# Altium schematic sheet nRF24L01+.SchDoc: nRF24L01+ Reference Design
size Letter
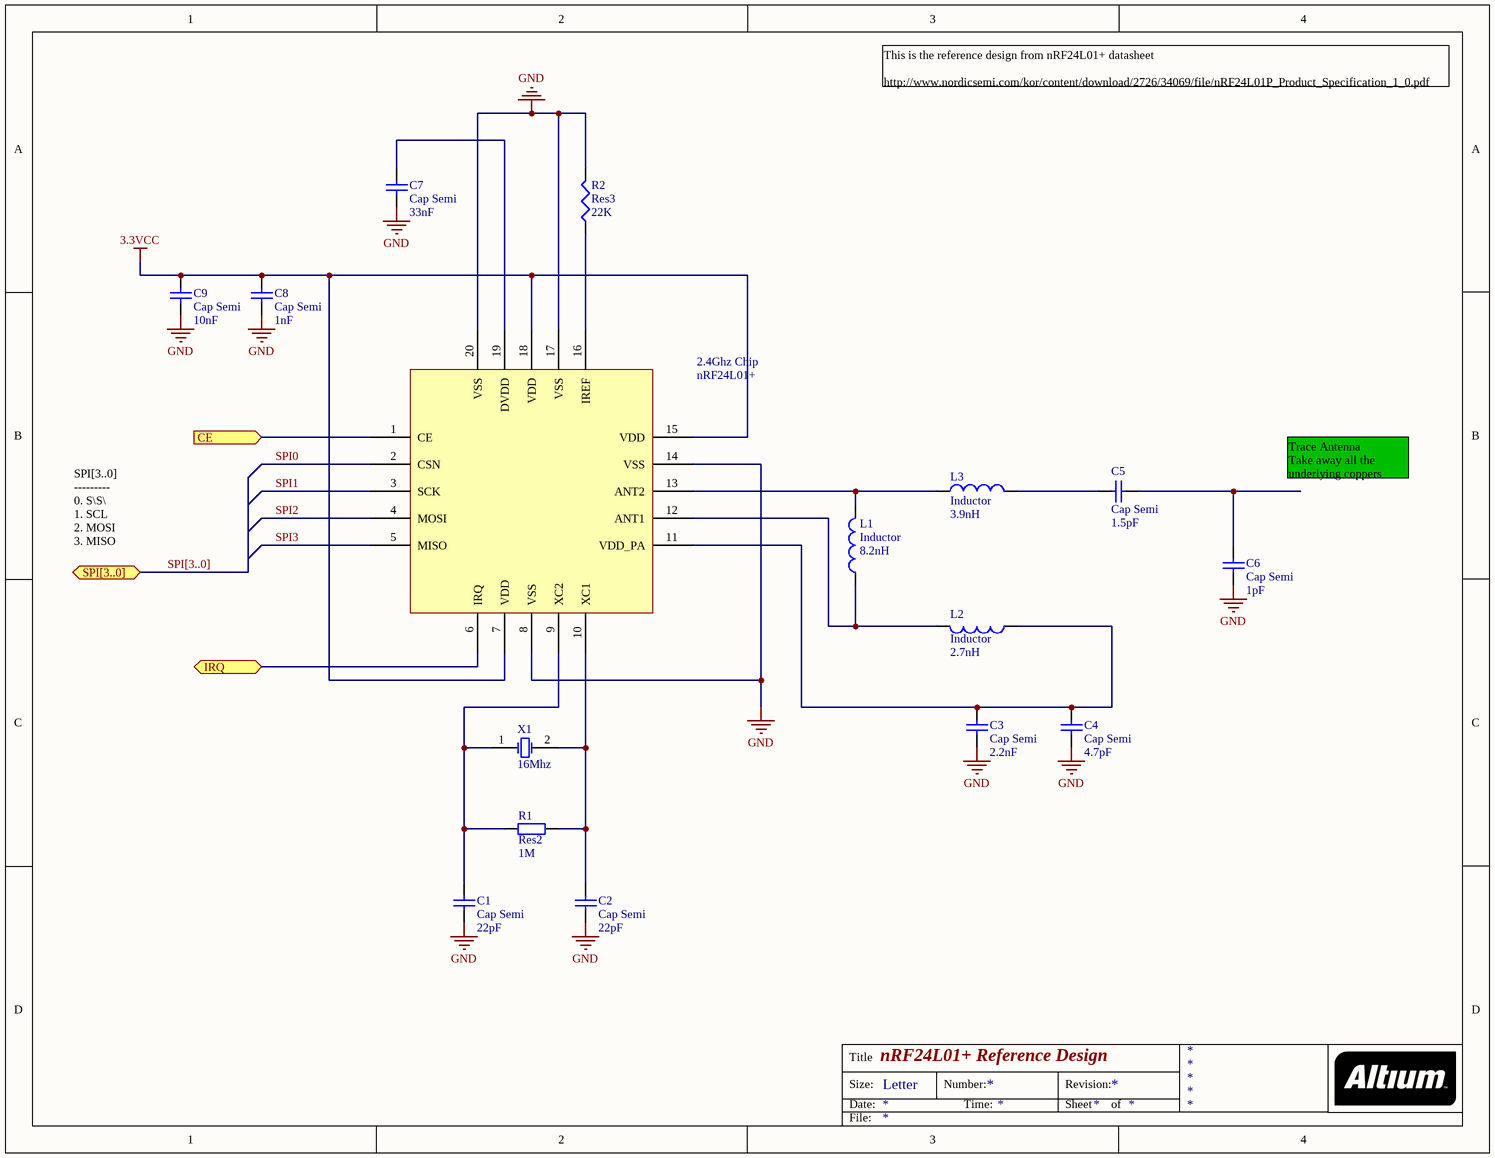
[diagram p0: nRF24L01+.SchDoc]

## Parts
2.4Ghz_Chip  nRF24L01+  [nRF24L01+]
C1  Cap Semi  value 22pF  [CAPC2012N]
C2  Cap Semi  value 22pF  [CAPC2012N]
C3  Cap Semi  value 2.2nF  [CAPC2012N]
C4  Cap Semi  value 4.7pF  [CAPC2012N]
C5  Cap Semi  value 1.5pF  [CAPC2012N]
C6  Cap Semi  value 1pF  [CAPC2012N]
C7  Cap Semi  value 33nF  [CAPC2012N]
C8  Cap Semi  value 1nF  [CAPC2012N]
C9  Cap Semi  value 10nF  [CAPC2012N]
L1  Inductor  value 8.2nH  [INDC1608N]
L2  Inductor  value 2.7nH  [INDC1608N]
L3  Inductor  value 3.9nH  [INDC1608N]
R1  Res2  value 1M  [RESC2012N]
R2  Res3  value 22K  [RESC2012N]
X1  16Mhz  [HC-49U - Through Hole]

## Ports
CE (in), IRQ, SPI[3..0] (bidir)

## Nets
3.3VCC: 2.4Ghz_Chip.7(VDD) 2.4Ghz_Chip.15(VDD) 2.4Ghz_Chip.18(VDD) C8.2 C9.2
GND: 2.4Ghz_Chip.8(VSS) 2.4Ghz_Chip.14(VSS) 2.4Ghz_Chip.17(VSS) 2.4Ghz_Chip.20(VSS) C1.1 C2.1 C3.1 C4.1 C6.1 C7.1 C8.1 C9.1 R2.2
CE: 2.4Ghz_Chip.1(CE) ; port CE
IRQ: 2.4Ghz_Chip.6(IRQ) ; port IRQ
SPI0: 2.4Ghz_Chip.2(CSN)
SPI1: 2.4Ghz_Chip.3(SCK)
SPI2: 2.4Ghz_Chip.4(MOSI)
SPI3: 2.4Ghz_Chip.5(MISO)
Net2.4Ghz_Chip_9: 2.4Ghz_Chip.9(XC2) C1.2 R1.1 X1.1(OSC1)
Net2.4Ghz_Chip_10: 2.4Ghz_Chip.10(XC1) C2.2 R1.2 X1.2(OSC2)
Net2.4Ghz_Chip_11: 2.4Ghz_Chip.11(VDD_PA) C3.2 C4.2 L2.1
Net2.4Ghz_Chip_12: 2.4Ghz_Chip.12(ANT1) L1.1 L2.2
Net2.4Ghz_Chip_13: 2.4Ghz_Chip.13(ANT2) L1.2 L3.1
Net2.4Ghz_Chip_16: 2.4Ghz_Chip.16(IREF) R2.1
Net2.4Ghz_Chip_19: 2.4Ghz_Chip.19(DVDD) C7.2
NetC5_1: C5.1 C6.2
NetC5_2: C5.2 L3.2

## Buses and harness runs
bus SPI[3..0] = port SPI[3..0]

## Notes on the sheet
- This is the reference design from nRF24L01+ datasheet
  http://www.nordicsemi.com/kor/content/download/2726/34069/file/nRF24L01P_Product_Specification_1_0.pdf
- Trace Antenna
  Take away all the underlying coppers (both side) from this area
- SPI[3..0]
  ---------
  0. S\S\
  1. SCL
  2. MOSI
  3. MISO

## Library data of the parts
C1-C9 = Cap Semi: Capacitor (Semiconductor SIM Model)
L1-L3 = Inductor: Code_IEC: 1005
R1 = Res2: Resistor
R2 = Res3: Resistor
X1 = XTAL: Crystal Oscillator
